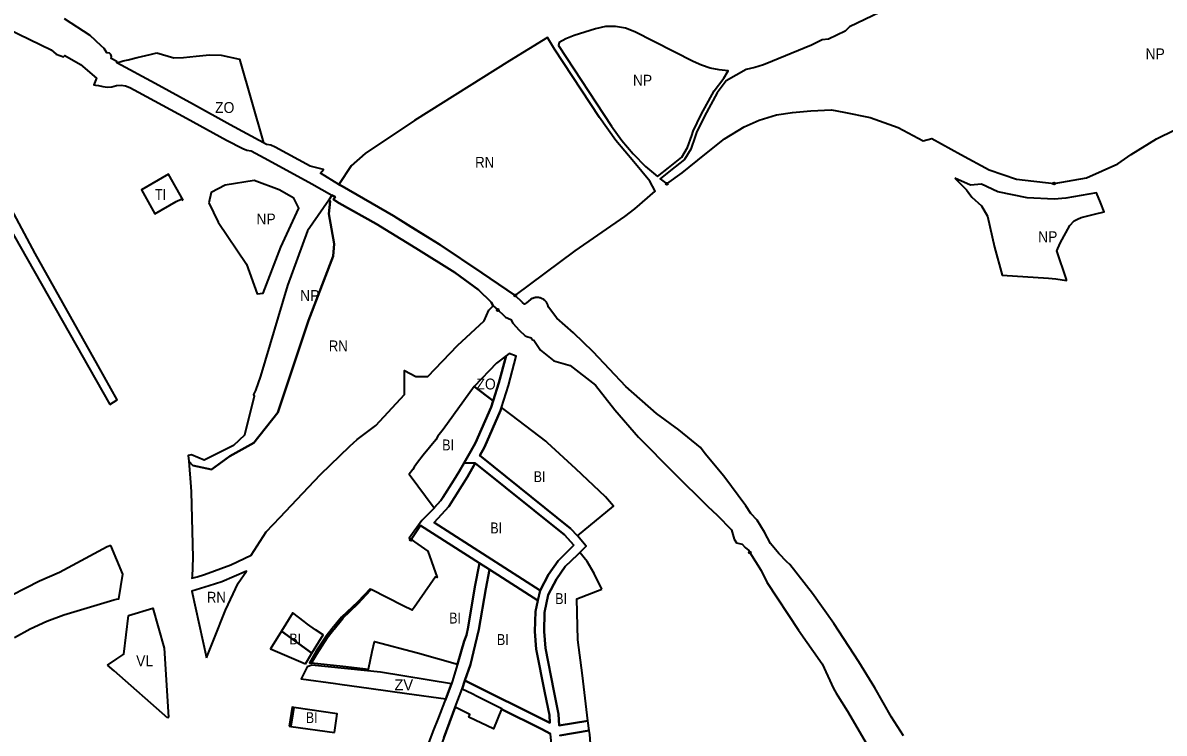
# Model space of a CAD drawing. Extents: x -650276 to -642489, y -1074311 to -1066658.
# Drawn here: x -646121 to -644867, y -1069647 to -1068866 of the extents above; entities that cross this region are included whole.
import ezdxf

# ---------------------------------------------------------------- set-up
doc = ezdxf.new("R2010")
doc.units = 0
doc.header["$LTSCALE"] = 4.8
doc.header["$PDMODE"] = 32
doc.header["$PDSIZE"] = 2.4
for name, color, linetype, lineweight in [('15', 7, 'Continuous', 35), ('2', 7, 'Continuous', 35), ('24', 7, 'Continuous', 35), ('30', 7, 'Continuous', 35), ('34', 7, 'Continuous', 35), ('40', 7, 'Continuous', 35), ('42', 7, 'Continuous', 35), ('48', 7, 'Continuous', 35), ('7', 7, 'Continuous', 35)]:
    doc.layers.add(name, color=color, linetype=linetype, lineweight=lineweight)
doc.layers.add('62', color=7, linetype='Continuous')
doc.layers.add('63', color=7, linetype='Continuous')

msp = doc.modelspace()

# ---------------------------------------------------------------- linework, layer by layer
at = {"layer": '15'}
for p, q in [((-645552.336, -1069489.579), (-645555.072, -1069500.545)), ((-645638.203, -1069597.8), (-645635.153, -1069588.78))]:
    msp.add_line(p, q, dxfattribs=at)
for points in [[(-646037.99, -1069242.88), (-646107, -1069119.41), (-646150.87, -1069037.64), (-646152.26, -1069038.76), (-646161.484, -1069046.228), (-646153.307, -1069059.947), (-646025.14, -1069285.394)], [(-645589.844, -1069231.908), (-645597.738, -1069261.522), (-645604.114, -1069281.49)], [(-645594.94, -1069288.511), (-645587.298, -1069264.578), (-645578.713, -1069232.375), (-645586.39, -1069229.32), (-645589.844, -1069231.908)], [(-646025.14, -1069285.394), (-646017.15, -1069280.19), (-646037.99, -1069242.88)], [(-645604.114, -1069281.49), (-645606.256, -1069288.199), (-645623.307, -1069327.508), (-645628.492, -1069336.506), (-645635.995, -1069349.527), (-645623.694, -1069349.962)], [(-645618.766, -1069341.409), (-645613.576, -1069332.402), (-645596.062, -1069292.027), (-645594.94, -1069288.511)], [(-645511.585, -1069450.466), (-645501.878, -1069440.838), (-645511.464, -1069429.794), (-645519.097, -1069421.579), (-645618.766, -1069341.409)], [(-645669.039, -1069415.116), (-645652.804, -1069397.548), (-645632.191, -1069364.707), (-645623.694, -1069349.962), (-645635.995, -1069349.527)], [(-645635.995, -1069349.527), (-645641.511, -1069359.099), (-645647.304, -1069368.329), (-645659.41, -1069387.617)], [(-645623.694, -1069349.962), (-645525.761, -1069428.736), (-645515.509, -1069439.769)], [(-645659.41, -1069387.617), (-645661.477, -1069390.91), (-645668.722, -1069398.75)], [(-645678.06, -1069408.54), (-645682.28, -1069412.88), (-645696.45, -1069432.21), (-645694.21, -1069433.78)], [(-645668.722, -1069398.75), (-645668.61, -1069398.9), (-645678.06, -1069408.54)], [(-645694.21, -1069433.78), (-645683.883, -1069418.357), (-645619.119, -1069459.68)], [(-645619.119, -1069459.68), (-645608.04, -1069466.749), (-645555.072, -1069500.545), (-645552.336, -1069489.579), (-645669.039, -1069415.116)], [(-645515.509, -1069439.769), (-645532.534, -1069456.978), (-645543.158, -1069472.134), (-645552.336, -1069489.579), (-645555.072, -1069500.545)], [(-645658.119, -1069651.601), (-645645.715, -1069618.085), (-645638.203, -1069597.8), (-645635.153, -1069588.78), (-645629.102, -1069570.857), (-645623.814, -1069549.548), (-645619.662, -1069532.642), (-645612.028, -1069487.724), (-645608.04, -1069466.749), (-645619.119, -1069459.68), (-645624.041, -1069485.561), (-645631.62, -1069530.161), (-645633.29, -1069538.7), (-645636.09, -1069545.31), (-645643.16, -1069570.6), (-645644.56, -1069575.61), (-645648.68, -1069589.06), (-645649.91, -1069592.39), (-645656.15, -1069608.71), (-645657.52, -1069612.2), (-645664.19, -1069629.24), (-645670.23, -1069644.67), (-645676.34, -1069660.28)], [(-645531.753, -1069637.96), (-645532.36, -1069625.648), (-645537.354, -1069600.095), (-645546.74, -1069552.954), (-645548.207, -1069534.609), (-645547.654, -1069514.049), (-645543.548, -1069494.404), (-645534.584, -1069477.365), (-645524.812, -1069463.425), (-645511.585, -1069450.466)], [(-645739.3, -1069487.81), (-645753.05, -1069502.47), (-645770.66, -1069519.07), (-645780.85, -1069531.55), (-645787.64, -1069539.88), (-645798.53, -1069556.3), (-645805.66, -1069569.03), (-645803.513, -1069569.263)], [(-645752.715, -1069504.328), (-645738.986, -1069489.868), (-645737.897, -1069488.534), (-645739.3, -1069487.81)], [(-645803.513, -1069569.263), (-645798.102, -1069559.972), (-645786.388, -1069541.673), (-645779.376, -1069532.962), (-645778.754, -1069532.198), (-645769.369, -1069520.672), (-645768.995, -1069520.305), (-645752.715, -1069504.328)], [(-645555.072, -1069500.545), (-645557.65, -1069512.879), (-645558.241, -1069534.874), (-645556.685, -1069554.337), (-645547.188, -1069602.035), (-645542.336, -1069626.862), (-645541.922, -1069635.264), (-645635.153, -1069588.78), (-645638.203, -1069597.8)], [(-645638.203, -1069597.8), (-645626.95, -1069602.91), (-645621.56, -1069605.68), (-645594.58, -1069619.56), (-645594.818, -1069620.139), (-645550.62, -1069642.176), (-645541.064, -1069647.092)], [(-645826.151, -1069639.057), (-645826.133, -1069638.843), (-645825.295, -1069632.053), (-645823.13, -1069618.452), (-645823.082, -1069618.279), (-645824.95, -1069618.01), (-645827.94, -1069638.8)], [(-645530.797, -1069648.949), (-645498.61, -1069643.729), (-645500.137, -1069632.833), (-645531.753, -1069637.96)], [(-645827.94, -1069638.8), (-645826.149, -1069639.082), (-645826.151, -1069639.057)]]:
    msp.add_lwpolyline(points, dxfattribs=at)
msp.add_point((-645694.21, -1069433.78), dxfattribs=at)
at = {"layer": '2'}
for points in [[(-645628.492, -1069336.506), (-645623.307, -1069327.508), (-645606.256, -1069288.199), (-645604.114, -1069281.49), (-645625.11, -1069265.42), (-645658.9, -1069312.83), (-645664.89, -1069320.2), (-645667, -1069324.06), (-645680.8, -1069341.08), (-645687.22, -1069349), (-645690.81, -1069354.28), (-645692.38, -1069356.67), (-645696.19, -1069362.01), (-645668.722, -1069398.75)], [(-645594.94, -1069288.511), (-645596.062, -1069292.027), (-645613.576, -1069332.402), (-645618.766, -1069341.409), (-645519.097, -1069421.579)], [(-645519.097, -1069421.579), (-645511.464, -1069429.794), (-645471.738, -1069397.026), (-645480.72, -1069386.96), (-645513.41, -1069356.18), (-645544.26, -1069327.35), (-645546.19, -1069325.81), (-645583.13, -1069297.55), (-645594.94, -1069288.511)], [(-645647.304, -1069368.329), (-645641.511, -1069359.099), (-645635.995, -1069349.527), (-645628.492, -1069336.506)], [(-645623.694, -1069349.962), (-645632.191, -1069364.707), (-645652.804, -1069397.548), (-645669.039, -1069415.116), (-645552.336, -1069489.579)], [(-645515.509, -1069439.769), (-645525.761, -1069428.736), (-645623.694, -1069349.962)], [(-645668.722, -1069398.75), (-645661.477, -1069390.91), (-645659.41, -1069387.617), (-645647.304, -1069368.329)], [(-645552.336, -1069489.579), (-645543.158, -1069472.134), (-645532.534, -1069456.978), (-645515.509, -1069439.769)], [(-645484.783, -1069488.256), (-645493, -1069471), (-645501, -1069458), (-645508.994, -1069447.955), (-645511.585, -1069450.466)], [(-645511.585, -1069450.466), (-645524.812, -1069463.425), (-645534.584, -1069477.365), (-645543.548, -1069494.404), (-645547.654, -1069514.049), (-645548.207, -1069534.609)], [(-645608.04, -1069466.749), (-645612.028, -1069487.724), (-645619.662, -1069532.642), (-645623.814, -1069549.548), (-645629.102, -1069570.857), (-645635.153, -1069588.78), (-645541.922, -1069635.264)], [(-645541.922, -1069635.264), (-645542.336, -1069626.862), (-645547.188, -1069602.035), (-645556.685, -1069554.337), (-645558.241, -1069534.874), (-645557.65, -1069512.879), (-645555.072, -1069500.545), (-645608.04, -1069466.749)], [(-645500.137, -1069632.833), (-645506, -1069583), (-645511, -1069544), (-645512, -1069499), (-645484.783, -1069488.256)], [(-645548.207, -1069534.609), (-645546.74, -1069552.954), (-645537.354, -1069600.095)], [(-645537.354, -1069600.095), (-645532.36, -1069625.648), (-645531.753, -1069637.96), (-645500.137, -1069632.833)], [(-645823.082, -1069618.279), (-645823.13, -1069618.452), (-645825.295, -1069632.053), (-645826.133, -1069638.843), (-645826.151, -1069639.057), (-645778.45, -1069645.92)], [(-645778.45, -1069645.92), (-645775.46, -1069625.13), (-645823.082, -1069618.279)], [(-645645.715, -1069618.085), (-645658.119, -1069651.601), (-645665.961, -1069673.028), (-645602.91, -1069703.88), (-645546.93, -1069731.98), (-645538.579, -1069710.102)], [(-645538.15, -1069675.537), (-645538.744, -1069669.644), (-645541.064, -1069647.092), (-645550.62, -1069642.176), (-645594.818, -1069620.139), (-645603.7, -1069641.75), (-645630.93, -1069628.84), (-645629.78, -1069626.03), (-645645.715, -1069618.085)], [(-645495, -1069744), (-645495, -1069688), (-645498, -1069648), (-645498.61, -1069643.729), (-645530.793, -1069648.948), (-645530.757, -1069649.336)]]:
    msp.add_lwpolyline(points, dxfattribs=at)
for points in [[(-645778.754, -1069532.198), (-645779.376, -1069532.962), (-645786.388, -1069541.673), (-645798.102, -1069559.972), (-645803.513, -1069569.263), (-645769.04, -1069573), (-645741.14, -1069576.19), (-645736.8, -1069556.91), (-645734.5, -1069545.89), (-645687.29, -1069558.04), (-645643.16, -1069570.6), (-645636.09, -1069545.31), (-645633.29, -1069538.7), (-645631.62, -1069530.161), (-645624.041, -1069485.561), (-645619.119, -1069459.68), (-645683.883, -1069418.357), (-645694.21, -1069433.78), (-645675.91, -1069446.56), (-645665.58, -1069475.61), (-645667.31, -1069474.6), (-645690.84, -1069508.32), (-645692.87, -1069511.229), (-645702.82, -1069506.64), (-645737.897, -1069488.534), (-645738.986, -1069489.868), (-645752.715, -1069504.328), (-645768.995, -1069520.305), (-645769.369, -1069520.672)], [(-645803.07, -1069558.62), (-645790.62, -1069538.59), (-645799.07, -1069532.8), (-645808.1, -1069526.61), (-645811.75, -1069523.81), (-645824.05, -1069514.34), (-645836.44, -1069534.5)], [(-645810.08, -1069570.39), (-645803.07, -1069558.62), (-645836.44, -1069534.5), (-645848.78, -1069553.91)]]:
    msp.add_lwpolyline(points, close=True, dxfattribs=at)
at = {"layer": '24'}
for points in [[(-645579.94, -1069165.52), (-645616.63, -1069140.8), (-645662.44, -1069109.89), (-645713.61, -1069078.06), (-645770.04, -1069045.34), (-645773.38, -1069043.46), (-645793.638, -1069031.021), (-645790.53, -1069027.19), (-645805.16, -1069023.52), (-645843.56, -1069002.41), (-645848.18, -1069000.48), (-645852.91, -1068999.62), (-645856.26, -1068997.79), (-645892.77, -1068977.86), (-645933.28, -1068955.74), (-645975.31, -1068932.8), (-646017.55, -1068909.75), (-646017.39, -1068908.42), (-646023.56, -1068905.05), (-646023.13, -1068903.12), (-646023.92, -1068900.73), (-646025.57, -1068899.39), (-646028.18, -1068898.89), (-646031.31, -1068894.32), (-646034.65, -1068891.12), (-646046.48, -1068879.92), (-646074.78, -1068861.51)], [(-646137.23, -1068872.6), (-646089.63, -1068895.5), (-646084.1, -1068900.51), (-646076.09, -1068903.48), (-646074.51, -1068901.9), (-646057.13, -1068911.62), (-646039.84, -1068926.67), (-646042.5, -1068933.91), (-646040.65, -1068934.59), (-646037.5, -1068934.7), (-646032.61, -1068936.1), (-646027.69, -1068936.6), (-646022.77, -1068936.12), (-646017.6, -1068934.89), (-646012.64, -1068934.34), (-646007.7, -1068935.18), (-646002.95, -1068936.95), (-645993.5, -1068942.1), (-645940.77, -1068970.74), (-645896.91, -1068994.75), (-645879.17, -1069004.02), (-645874.49, -1069005.73), (-645869.83, -1069006.45), (-645850.79, -1069016.84), (-645803.29, -1069042.92), (-645781.12, -1069055.29), (-645777.73, -1069057.2), (-645779.49, -1069059.92), (-645773.29, -1069063.99), (-645732.65, -1069086.82), (-645688.87, -1069113.44), (-645646.08, -1069140.37), (-645620.2, -1069159.26), (-645606.11, -1069172.98), (-645603.91, -1069176.86), (-645599, -1069181.48)], [(-645571.9, -1069173.43), (-645579.94, -1069165.52), (-645579.94, -1069165.52)], [(-645543.43, -1069178.39), (-645543.547, -1069177.727), (-645543.706, -1069177.053), (-645543.907, -1069176.37), (-645544.154, -1069175.682), (-645544.448, -1069174.993), (-645544.792, -1069174.308), (-645545.186, -1069173.63), (-645545.631, -1069172.966), (-645546.127, -1069172.32), (-645546.674, -1069171.699), (-645547.269, -1069171.107), (-645547.91, -1069170.551), (-645548.594, -1069170.034), (-645549.317, -1069169.563), (-645550.076, -1069169.141), (-645550.863, -1069168.772), (-645551.674, -1069168.459), (-645552.504, -1069168.203), (-645553.344, -1069168.007), (-645554.191, -1069167.87), (-645555.036, -1069167.793), (-645555.875, -1069167.772), (-645556.702, -1069167.808), (-645557.511, -1069167.896), (-645558.298, -1069168.035), (-645559.06, -1069168.219), (-645559.793, -1069168.445), (-645560.494, -1069168.709), (-645561.162, -1069169.007), (-645561.794, -1069169.334), (-645562.39, -1069169.686), (-645562.95, -1069170.06), (-645567.5, -1069173.46), (-645569.81, -1069175.03), (-645571.9, -1069173.43)], [(-645599, -1069181.48), (-645599, -1069181.48), (-645592.24, -1069187.73), (-645590.41, -1069189.45), (-645584.73, -1069191.88), (-645582.63, -1069195.88), (-645575.58, -1069203.57), (-645568.9, -1069209.87), (-645567.07, -1069210.45), (-645562.17, -1069212.02), (-645560.72, -1069214.25), (-645559.33, -1069214.54), (-645552.2, -1069225.59), (-645537.44, -1069237.41), (-645519.59, -1069242.38), (-645491.63, -1069264.25), (-645470.44, -1069291.24), (-645444.62, -1069321.35), (-645405.7, -1069360.27), (-645368.13, -1069397.37), (-645358.04, -1069406.84), (-645342.49, -1069423.06), (-645339.31, -1069433.27), (-645336.66, -1069437.47), (-645330.57, -1069438.89), (-645327.2, -1069442.53), (-645323.36, -1069445.79), (-645322.13, -1069447.96)], [(-645153.33, -1069649.24), (-645166.67, -1069629), (-645184.88, -1069596.58), (-645202.56, -1069568.23), (-645230.1, -1069525.98), (-645253.4, -1069493.06), (-645278.31, -1069461.33), (-645281.4, -1069458.4), (-645290.5, -1069449.03), (-645299.61, -1069437.97), (-645306.16, -1069425.55), (-645314.14, -1069412.54), (-645321.1, -1069405.21), (-645326.59, -1069396.64), (-645350.63, -1069363.98), (-645371.12, -1069339.47), (-645376.38, -1069332.65), (-645400.07, -1069313.32), (-645424.8, -1069295.24), (-645458.45, -1069265.56), (-645494.13, -1069227.63), (-645515.89, -1069206.66), (-645534.25, -1069190.56), (-645543.43, -1069178.39)], [(-645322.13, -1069447.96), (-645309.62, -1069467.79), (-645303.57, -1069480.49), (-645268.57, -1069533.23), (-645242.75, -1069570.26), (-645230.42, -1069597.39), (-645227.27, -1069602.68), (-645225.7, -1069605.32), (-645214.76, -1069622.37), (-645198.41, -1069650.49), (-645185.17, -1069673.38), (-645179.12, -1069681.3), (-645170.3, -1069698.91), (-645158.43, -1069722.61), (-645153.44, -1069734.71), (-645140.27, -1069766.68), (-645123.84, -1069805.38), (-645108.74, -1069843.58), (-645094.42, -1069882.65), (-645083.31, -1069913.37), (-645071.53, -1069948.89), (-645063.96, -1069973.73), (-645063.23, -1069976.2), (-645062.57, -1069978.46)]]:
    msp.add_lwpolyline(points, dxfattribs=at)
for p in [(-645579.94, -1069165.52), (-645599, -1069181.48), (-645322.13, -1069447.96)]:
    msp.add_point(p, dxfattribs=at)
at = {"layer": '30'}
msp.add_lwpolyline([(-645944.69, -1069060.7), (-645960.67, -1069032.26), (-645990.13, -1069049.3), (-645975.48, -1069075.71), (-645952.21, -1069062.4), (-645946.84, -1069059.58)], close=True, dxfattribs=at)
for points in [[(-645944.69, -1069060.7), (-645960.67, -1069032.26), (-645990.13, -1069049.3), (-645975.48, -1069075.71), (-645952.21, -1069062.4)], [(-645952.21, -1069062.4), (-645946.84, -1069059.58), (-645944.69, -1069060.7)]]:
    msp.add_lwpolyline(points, dxfattribs=at)
at = {"layer": '34'}
for points in [[(-646004.7, -1069517.16), (-645977.73, -1069509.11), (-645965.36, -1069552.99), (-645960.78, -1069628.91), (-645961.36, -1069630.05)], [(-646027.49, -1069571.79), (-646017.39, -1069564.94), (-646009.52, -1069559.6), (-646004.7, -1069517.16)], [(-645961.36, -1069630.05), (-646020.4, -1069578.04), (-646027.49, -1069571.79)]]:
    msp.add_lwpolyline(points, dxfattribs=at)
at = {"layer": '40'}
msp.add_lwpolyline([(-645698.83, -1069602.85), (-645656.15, -1069608.71), (-645649.91, -1069592.39), (-645727.71, -1069579.61), (-645803.33, -1069571.62), (-645808.18, -1069573.7), (-645814.82, -1069586.81), (-645777.26, -1069592.07), (-645772.58, -1069592.73), (-645738.13, -1069597.46)], close=True, dxfattribs=at)
at = {"layer": '42'}
for points in [[(-646017.55, -1068909.75), (-646010.48, -1068907.86), (-646004.88, -1068906.5), (-645994.9, -1068904.1), (-645980.93, -1068900.85), (-645973.36, -1068898.93)], [(-645973.36, -1068898.93), (-645954.59, -1068904.41), (-645944.23, -1068904.13), (-645930.1, -1068902.47), (-645915.61, -1068901.02), (-645902.91, -1068901.43), (-645882.63, -1068905.88), (-645856.26, -1068997.79)], [(-645856.26, -1068997.79), (-645892.77, -1068977.86), (-645933.28, -1068955.74), (-645975.31, -1068932.8), (-646017.55, -1068909.75)], [(-646023.96, -1069440.34), (-646028.16, -1069441.58), (-646080.35, -1069469.89), (-646102.15, -1069479.49), (-646148.5, -1069503), (-646146.8, -1069506.6), (-646189.17, -1069528.74), (-646209.9, -1069538.5), (-646321.973, -1069686.855), (-646554.262, -1069762.602), (-646581.489, -1069759.421), (-646585.51, -1069769.57)], [(-646017.63, -1069499.08), (-646017.63, -1069499.08), (-646015.16, -1069498.74), (-646010.65, -1069471.91), (-646023.96, -1069440.34)], [(-646129.87, -1069541.19), (-646112.56, -1069531.78), (-646094.39, -1069523.34), (-646075.48, -1069516.38), (-646020.75, -1069500), (-646017.63, -1069499.08)]]:
    msp.add_lwpolyline(points, dxfattribs=at)
msp.add_lwpolyline([(-645604.114, -1069281.49), (-645597.738, -1069261.522), (-645589.844, -1069231.908), (-645600.55, -1069239.93), (-645625.11, -1069265.42)], close=True, dxfattribs=at)
at = {"layer": '48'}
for points in [[(-645119.5, -1068825.24), (-645212.72, -1068870.49), (-645217.45, -1068875.09), (-645235.76, -1068883.92), (-645242.64, -1068884.8), (-645254.58, -1068890.34), (-645276.91, -1068899.79), (-645297.15, -1068907.94), (-645307.16, -1068911.97), (-645316.51, -1068915.17), (-645326.23, -1068917.37)], [(-645423.753, -1069034.862), (-645411.68, -1069025.2), (-645397.01, -1069013.46), (-645390.75, -1069003.09), (-645386.05, -1068989.63), (-645384.4, -1068984.91), (-645375.53, -1068966.56), (-645361.36, -1068940.57), (-645350.78, -1068926.76), (-645346.11, -1068918.62), (-645356.04, -1068917.65), (-645365.8, -1068915.63), (-645375.3, -1068912.58), (-645384.33, -1068908.58), (-645448.43, -1068875.95), (-645458.84, -1068871.88), (-645469.68, -1068869.93), (-645480.68, -1068870.12), (-645491.61, -1068872.47), (-645515.12, -1068880), (-645524.13, -1068883.52), (-645531.66, -1068887.61), (-645532.39, -1068890.9), (-645473.98, -1068979.47)], [(-645326.23, -1068917.37), (-645348.066, -1068929.794), (-645357.996, -1068942.757), (-645371.971, -1068968.389), (-645380.699, -1068986.445), (-645382.274, -1068990.949)], [(-645413.29, -1069042.92), (-645396.53, -1069030.88), (-645371.56, -1069010.81), (-645350.17, -1068993.33), (-645328.55, -1068980.37), (-645311.99, -1068972.74), (-645292.77, -1068966.91), (-645275.45, -1068964.38), (-645255.21, -1068962.49), (-645232.4, -1068961.67), (-645218.85, -1068964.3), (-645189.84, -1068969.91), (-645159.37, -1068981.11), (-645131.73, -1068995.69), (-645122.25, -1068993.21), (-645090.35, -1069010.56), (-645059.3, -1069027.45), (-645029.47, -1069037.71), (-644988.11, -1069042.51)], [(-645473.98, -1068979.47), (-645462.64, -1068995.27), (-645450.17, -1069010.02), (-645436.6, -1069023.76), (-645423.753, -1069034.862)], [(-644875.57, -1068993.47), (-644855.56, -1068983.38), (-644803.31, -1068986.97), (-644785.78, -1068986.13), (-644761.88, -1068986.27), (-644750.67, -1068986.34), (-644708.6, -1068984.54), (-644683, -1068984.03), (-644667.57, -1068983.47), (-644665.41, -1068983.39), (-644657.61, -1068983.91)], [(-645382.274, -1068990.949), (-645387.111, -1069004.801), (-645393.954, -1069016.138), (-645409.181, -1069028.323), (-645420.586, -1069037.45), (-645413.29, -1069042.92)], [(-644988.11, -1069042.51), (-644952.47, -1069036.35), (-644918.04, -1069020.91), (-644903.21, -1069010.69), (-644875.57, -1068993.47)], [(-645096.97, -1069036.63), (-645084.19, -1069049.55), (-645078.47, -1069057.37), (-645067.57, -1069067.16)], [(-644993.99, -1069146.57), (-644994.006, -1069146.673), (-644986.221, -1069147.139), (-644974.505, -1069149.05), (-644974.34, -1069147.85), (-644985.15, -1069116.67), (-644981.3, -1069108.22), (-644970.84, -1069088.8), (-644965.95, -1069083.67), (-644962.15, -1069081.85), (-644958.25, -1069079.99), (-644943.69, -1069076.34), (-644932.95, -1069073.65), (-644937.058, -1069063.404), (-644937.057, -1069063.403), (-644937.05, -1069063.4), (-644941.27, -1069052.9), (-644975.19, -1069058.65), (-644987.99, -1069059.67), (-645017.77, -1069058.35), (-645049.91, -1069051.48), (-645067.65, -1069043.18), (-645079.65, -1069044.32), (-645096.97, -1069036.63)], [(-645096.97, -1069036.63), (-645084.19, -1069049.55), (-645080.589, -1069054.473)], [(-645080.589, -1069054.473), (-645078.47, -1069057.37), (-645067.57, -1069067.16), (-645061.2, -1069078.47), (-645053.61, -1069112.32), (-645044.97, -1069143.38), (-644993.99, -1069146.57)]]:
    msp.add_lwpolyline(points, dxfattribs=at)
for points in [[(-645916.2, -1069063.8), (-645905.94, -1069085.11), (-645874.98, -1069131.01), (-645863.38, -1069163.79), (-645856.76, -1069163.17), (-645837.21, -1069112.54), (-645817.59, -1069069.6), (-645822.85, -1069058.8), (-645838.99, -1069049.31), (-645866.69, -1069039.37), (-645898.57, -1069044.24), (-645913.8, -1069052.51)], [(-645877.15, -1069319.06), (-645877.15, -1069319.06), (-645889.29, -1069330.52), (-645921.56, -1069346.6), (-645935.33, -1069340.64), (-645938.89, -1069341.56), (-645938.399, -1069347.452), (-645933.792, -1069352.53), (-645913.23, -1069356.892), (-645893.291, -1069341.938), (-645867.026, -1069327.317), (-645840.644, -1069294.052), (-645806.806, -1069193.112), (-645779.685, -1069122.296), (-645778.75, -1069108.98), (-645784.52, -1069075.66), (-645783.02, -1069061.84), (-645784.69, -1069060.74), (-645807.89, -1069094.51), (-645829.96, -1069154.65), (-645859.43, -1069254.08), (-645864.96, -1069269.78), (-645867.42, -1069274.21), (-645866.45, -1069276.32)]]:
    msp.add_lwpolyline(points, close=True, dxfattribs=at)
for p in [(-645413.29, -1069042.92), (-644988.11, -1069042.51)]:
    msp.add_point(p, dxfattribs=at)
at = {"layer": '7'}
msp.add_line((-645918.82, -1069563.81), (-645910.9, -1069543.64), dxfattribs=at)
for points in [[(-645770.04, -1069045.34), (-645713.61, -1069078.06), (-645694.447, -1069089.98), (-645662.44, -1069109.89), (-645616.63, -1069140.8), (-645579.94, -1069165.52), (-645514.08, -1069116.5), (-645459.5, -1069078.59), (-645448.49, -1069070.45), (-645426.3, -1069051.02), (-645431.85, -1069039.83), (-645449.72, -1069018.58), (-645469.5, -1068995.09), (-645487.38, -1068969.87), (-645536.63, -1068894.79), (-645544.33, -1068882.17), (-645586.28, -1068907.71), (-645690.34, -1068973.16), (-645744.65, -1069009.71), (-645760.07, -1069023.11), (-645773.38, -1069043.46)], [(-645784.69, -1069060.74), (-645783.02, -1069061.84), (-645784.52, -1069075.66), (-645778.75, -1069108.98), (-645779.685, -1069122.296), (-645806.806, -1069193.112), (-645840.644, -1069294.052), (-645867.026, -1069327.317), (-645893.291, -1069341.938), (-645913.23, -1069356.892), (-645933.792, -1069352.53), (-645938.399, -1069347.452), (-645936.046, -1069375.651), (-645935.58, -1069381.24), (-645933.97, -1069453.52), (-645934.8, -1069474.71), (-645935.05, -1069476.32), (-645928.99, -1069474.55), (-645921.13, -1069472.25), (-645892.03, -1069461.43), (-645869.91, -1069451.02), (-645853.28, -1069425.27), (-645838.17, -1069409.28), (-645819.62, -1069389.66), (-645793.63, -1069362.15), (-645761.411, -1069331.17), (-645753.58, -1069323.64), (-645733.1, -1069308.58), (-645701.62, -1069274.36), (-645701.33, -1069247.86), (-645689, -1069254.5), (-645675.82, -1069254.48), (-645643.34, -1069220.59), (-645613.9, -1069193.45), (-645608.71, -1069181.51), (-645603.91, -1069176.86), (-645606.11, -1069172.98), (-645620.2, -1069159.26), (-645646.08, -1069140.37), (-645688.87, -1069113.44), (-645732.65, -1069086.82), (-645773.29, -1069063.99), (-645779.49, -1069059.92), (-645777.73, -1069057.2), (-645781.12, -1069055.29)]]:
    msp.add_lwpolyline(points, close=True, dxfattribs=at)
msp.add_lwpolyline([(-645910.9, -1069543.64), (-645897.92, -1069511.49), (-645884.01, -1069481.56), (-645875.02, -1069468.52), (-645902.19, -1069480.13), (-645916.13, -1069484.55), (-645934.97, -1069490.31), (-645918.82, -1069563.81)], dxfattribs=at)

# ---------------------------------------------------------------- texts
at = {"layer": '62'}
for s, width, p in [('NP', 0.95, (-644887.583, -1068906.041)), ('NP', 0.95, (-645450.583, -1068935.041)), ('ZO', 0.95, (-645909.476, -1068965.017)), ('RN', 0.9, (-645623.83, -1069025.21)), ('TI', 0.85, (-645975.476, -1069060.535)), ('NP', 0.95, (-645864.111, -1069087.517)), ('NP', 0.95, (-645005.583, -1069107.041)), ('NP', 0.95, (-645816.111, -1069171.517)), ('RN', 0.9, (-645784.603, -1069226.978)), ('ZO', 0.95, (-645622.428, -1069268.829)), ('BI', 0.85, (-645659.967, -1069335.79)), ('BI', 0.85, (-645559.537, -1069370.602)), ('BI', 0.85, (-645607.166, -1069426.988)), ('RN', 0.9, (-645918.459, -1069503.176)), ('BI', 0.85, (-645535.874, -1069504.638)), ('BI', 0.85, (-645652.376, -1069526.009)), ('BI', 0.85, (-645827.899, -1069548.998)), ('BI', 0.85, (-645599.874, -1069549.638)), ('BI', 0.85, (-645809.789, -1069635.433))]:
    msp.add_text(s, height=12, dxfattribs=dict(at, width=width)).set_placement(p)
msp.add_text('ZV', height=12, dxfattribs=at).set_placement((-645712.51, -1069599.456))
at = {"layer": '63', "width": 0.95}
msp.add_text('VL', height=12, dxfattribs=at).set_placement((-645996.15, -1069572.972))

doc.saveas('drawing.dxf')
